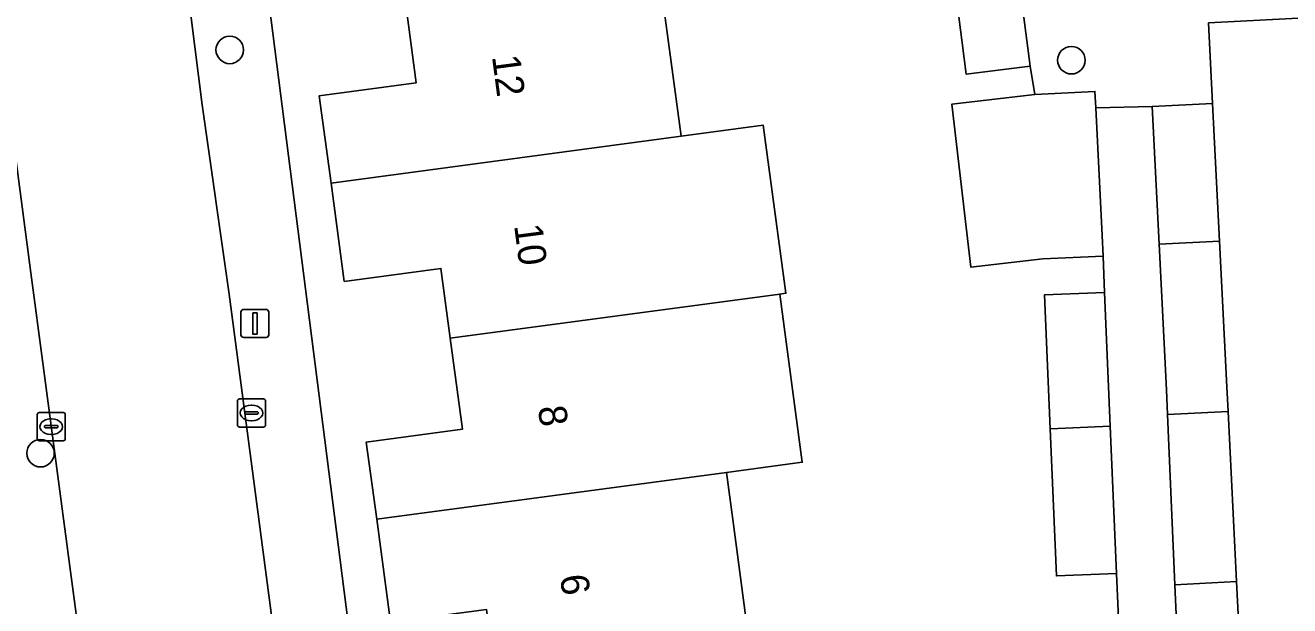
# Model space of a CAD drawing. Extents: x 161084 to 161928, y 385354 to 386522.
# Drawn here: x 161256.68 to 161301.64, y 385899.73 to 385920.36 of the extents above; entities that cross this region are included whole.
import ezdxf

# ---------------------------------------------------------------- set-up
doc = ezdxf.new("R2010")
doc.units = 0
for name, color, linetype in [('IMGEO_Boom', 7, 'Continuous'), ('IMGEO_Erf', 7, 'Continuous'), ('IMGEO_Kolk', 7, 'Continuous'), ('IMGEO_Lichtmast', 7, 'Continuous'), ('IMGEO_Pand', 7, 'Continuous'), ('IMGEO_Pand_nummerreeks', 7, 'Continuous'), ('IMGEO_Rijbaan_lokaal_open', 7, 'Continuous'), ('IMGEO_Voetpad_open', 7, 'Continuous')]:
    doc.layers.add(name, color=color, linetype=linetype)

msp = doc.modelspace()

# ---------------------------------------------------------------- linework, layer by layer
at = {"layer": 'IMGEO_Boom'}
for centre in [(161263.949, 385919.488), (161293.875, 385919.121), (161257.222, 385905.148)]:
    msp.add_circle(centre, 0.489, dxfattribs=at)
at = {"layer": 'IMGEO_Erf'}
for points in [[(161263.568, 385935.025), (161269.725, 385886.874)], [(161286.845, 385886.525), (161289.925, 385886.655), (161293.004, 385886.785), (161293.943, 385886.825), (161296.084, 385886.915), (161296.008, 385888.692), (161293.867, 385888.6), (161293.638, 385893.923), (161293.436, 385898.643), (161295.576, 385898.735), (161295.484, 385900.878), (161293.344, 385900.786), (161293.119, 385906.013), (161292.914, 385910.777), (161295.055, 385910.869), (161295, 385912.152), (161292.859, 385912.061), (161290.297, 385911.765), (161289.627, 385917.565), (161292.571, 385917.905), (161292.404, 385918.912), (161290.135, 385918.622), (161289.517, 385923.466)], [(161279.2, 385922.394), (161280.002, 385916.419), (161282.92, 385916.811), (161283.722, 385910.836), (161283.504, 385910.807), (161284.307, 385904.83), (161281.607, 385904.468), (161281.832, 385902.791), (161282.409, 385898.493)], [(161325.018, 385898.655), (161324.711, 385904.648), (161324.394, 385910.84), (161324.09, 385916.792), (161323.835, 385921.765), (161298.756, 385920.449), (161298.899, 385917.584), (161299.144, 385912.692), (161299.404, 385907.511), (161299.448, 385906.638), (161299.751, 385900.585), (161300.054, 385894.529), (161300.357, 385888.476), (161300.63, 385883.012), (161300.661, 385882.421), (161300.891, 385878.117), (161298.585, 385877.992), (161298.584, 385877.782), (161323.674, 385871.676)], [(161269.664, 385899.139), (161269.173, 385902.799), (161268.804, 385905.545), (161272.222, 385906.004), (161271.788, 385909.234), (161271.455, 385911.718), (161268.02, 385911.257), (161267.551, 385914.748), (161267.134, 385917.858), (161270.583, 385918.321), (161270.199, 385921.186)]]:
    msp.add_lwpolyline(points, dxfattribs=at)
at = {"layer": 'IMGEO_Kolk'}
for p, q in [((161264.223, 385906.154), (161264.223, 385907.006)), ((161264.298, 385907.08), (161265.15, 385907.08)), ((161264.711, 385906.86), (161264.736, 385906.86)), ((161265.224, 385907.006), (161265.224, 385906.154)), ((161257.101, 385905.668), (161257.101, 385906.52)), ((161257.176, 385906.594), (161258.028, 385906.594)), ((161257.589, 385906.374), (161257.614, 385906.374)), ((161258.102, 385906.52), (161258.102, 385905.668)), ((161264.482, 385906.574), (161264.482, 385906.586)), ((161264.92, 385906.537), (161264.522, 385906.537)), ((161264.525, 385906.623), (161264.923, 385906.623)), ((161264.966, 385906.586), (161264.966, 385906.574)), ((161257.36, 385906.088), (161257.36, 385906.1)), ((161257.798, 385906.051), (161257.4, 385906.051)), ((161257.403, 385906.137), (161257.801, 385906.137)), ((161257.844, 385906.1), (161257.844, 385906.088)), ((161265.15, 385906.08), (161264.298, 385906.08)), ((161264.734, 385906.3), (161264.709, 385906.3)), ((161258.028, 385905.594), (161257.176, 385905.594)), ((161257.612, 385905.814), (161257.587, 385905.814))]:
    msp.add_line(p, q, dxfattribs=at)
for points in [[(161264.223, 385906.154), (161264.223, 385907.006)], [(161264.298, 385907.08), (161265.15, 385907.08)], [(161265.224, 385907.006), (161265.224, 385906.154)], [(161257.101, 385905.668), (161257.101, 385906.52)], [(161257.176, 385906.594), (161258.028, 385906.594)], [(161258.102, 385906.52), (161258.102, 385905.668)], [(161265.15, 385906.08), (161264.298, 385906.08)], [(161258.028, 385905.594), (161257.176, 385905.594)]]:
    msp.add_lwpolyline(points, dxfattribs=at)
for centre, radius, start, end in [((161264.3, 385907.004), 0.0765, 91.552, 178.448), ((161264.3, 385907.004), 0.0765, 91.552, 178.448), ((161265.148, 385907.004), 0.0765, 1.552, 88.448), ((161265.148, 385907.004), 0.0765, 1.552, 88.448), ((161257.178, 385906.518), 0.0765, 91.552, 178.448), ((161257.178, 385906.518), 0.0765, 91.552, 178.448), ((161258.026, 385906.518), 0.0765, 1.552, 88.448), ((161258.026, 385906.518), 0.0765, 1.552, 88.448), ((161264.522, 385906.583), 0.0403, 85.8775, 175.7526), ((161264.519, 385906.573), 0.0366, 178.938, 274.7102), ((161264.923, 385906.58), 0.043, 264.8664, 352.4533), ((161264.927, 385906.585), 0.0386, 1.7309, 96.639), ((161257.4, 385906.097), 0.0403, 85.8775, 175.7526), ((161257.397, 385906.087), 0.0366, 178.938, 274.7102), ((161257.801, 385906.094), 0.043, 264.8664, 352.4533), ((161257.805, 385906.099), 0.0386, 1.7309, 96.639), ((161264.3, 385906.156), 0.0765, 181.552, 268.448), ((161264.3, 385906.156), 0.0765, 181.552, 268.448), ((161265.148, 385906.156), 0.0765, 271.552, 358.448), ((161265.148, 385906.156), 0.0765, 271.552, 358.448), ((161257.178, 385905.67), 0.0765, 181.552, 268.448), ((161257.178, 385905.67), 0.0765, 181.552, 268.448), ((161258.026, 385905.67), 0.0765, 271.552, 358.448), ((161258.026, 385905.67), 0.0765, 271.552, 358.448)]:
    msp.add_arc(centre, radius, start, end, dxfattribs=at)
for centre, major_axis, ratio, start_param, end_param in [((161264.71, 385906.58), (-0.387, 0.002), 0.722429, 4.712389, 7.853982), ((161264.735, 385906.58), (-0.39, 0.002), 0.717154, 1.570796, 4.712389), ((161257.588, 385906.094), (-0.387, 0.002), 0.722429, 4.712389, 7.853982), ((161257.613, 385906.094), (-0.39, 0.002), 0.717154, 1.570796, 4.712389)]:
    msp.add_ellipse(centre, major_axis=major_axis, ratio=ratio, start_param=start_param, end_param=end_param, dxfattribs=at)
at = {"layer": 'IMGEO_Lichtmast'}
for p, q in [((161264.348, 385909.362), (161264.348, 385910.162)), ((161264.348, 385910.162), (161264.348, 385909.362)), ((161264.448, 385910.262), (161265.238, 385910.262)), ((161265.238, 385910.262), (161264.448, 385910.262)), ((161265.338, 385910.162), (161265.338, 385909.362)), ((161265.338, 385909.362), (161265.338, 385910.162)), ((161265.238, 385909.262), (161264.448, 385909.262)), ((161264.448, 385909.262), (161265.238, 385909.262))]:
    msp.add_line(p, q, dxfattribs=at)
msp.add_lwpolyline([(161264.768, 385910.137), (161264.918, 385910.137), (161264.918, 385909.387), (161264.768, 385909.387), (161264.768, 385910.137)], dxfattribs=at)
for centre, start, end in [((161264.448, 385910.162), 90, 180), ((161264.448, 385910.162), 90, 180), ((161265.238, 385910.162), 0, 90), ((161265.238, 385910.162), 360, 90), ((161264.448, 385909.362), 180, 270), ((161264.448, 385909.362), 180, 270), ((161265.238, 385909.362), 270, 0), ((161265.238, 385909.362), 270, 0)]:
    msp.add_arc(centre, 0.1, start, end, dxfattribs=at)
at = {"layer": 'IMGEO_Pand'}
for points in [[(161291.786, 385923.756), (161291.317, 385923.696), (161289.517, 385923.466), (161290.135, 385918.622), (161292.404, 385918.912)], [(161280.002, 385916.419), (161279.2, 385922.394), (161270.199, 385921.186), (161270.583, 385918.321), (161267.134, 385917.858), (161267.551, 385914.748)], [(161294.74, 385917.43), (161294.711, 385918.012), (161292.571, 385917.905), (161289.627, 385917.565), (161290.297, 385911.765), (161292.859, 385912.061), (161295, 385912.152), (161294.968, 385912.888)], [(161296.751, 385917.476), (161296.997, 385912.579), (161299.144, 385912.692), (161298.899, 385917.584)], [(161282.92, 385916.811), (161280.002, 385916.419), (161267.551, 385914.748), (161268.02, 385911.257), (161271.455, 385911.718), (161271.788, 385909.234), (161283.504, 385910.807), (161283.722, 385910.836)], [(161299.448, 385906.638), (161299.404, 385907.511), (161299.144, 385912.692), (161296.997, 385912.579), (161297.256, 385907.403), (161297.294, 385906.525)], [(161295.055, 385910.869), (161292.914, 385910.777), (161293.119, 385906.013), (161293.133, 385906.015), (161295.259, 385906.106)], [(161283.504, 385910.807), (161271.788, 385909.234), (161272.222, 385906.004), (161268.804, 385905.545), (161269.173, 385902.799), (161281.607, 385904.468), (161284.307, 385904.83)], [(161299.751, 385900.585), (161299.448, 385906.638), (161297.294, 385906.525), (161297.558, 385900.471)], [(161295.259, 385906.106), (161293.133, 385906.015), (161293.119, 385906.013), (161293.344, 385900.786), (161295.484, 385900.878)], [(161282.409, 385898.493), (161281.832, 385902.791), (161281.607, 385904.468), (161269.173, 385902.799), (161269.664, 385899.139), (161273.076, 385899.597), (161273.387, 385897.282)], [(161300.054, 385894.529), (161299.751, 385900.585), (161297.558, 385900.471), (161297.822, 385894.411)]]:
    msp.add_lwpolyline(points, close=True, dxfattribs=at)
at = {"layer": 'IMGEO_Rijbaan_lokaal_open'}
for points in [[(161248.067, 385978.597), (161256.871, 385911.557), (161257.309, 385908.263), (161258.033, 385902.817), (161258.922, 385896.131), (161260.168, 385886.756), (161260.415, 385885.391), (161260.782, 385884.053), (161261.033, 385883.337), (161261.516, 385882.059), (161262.143, 385880.777), (161262.923, 385879.579), (161263.827, 385878.528), (161264.804, 385877.517), (161265.77, 385876.664), (161266.781, 385875.85), (161267.827, 385875.24), (161268.907, 385874.769), (161270.024, 385874.279), (161271.217, 385873.952), (161271.458, 385873.896), (161276.452, 385872.742), (161278.079, 385879.424), (161273.199, 385880.655)], [(161267.007, 385887.426), (161263.934, 385910.799), (161262.973, 385917.539), (161260.642, 385935.92)], [(161291.786, 385923.756), (161292.404, 385918.912), (161292.571, 385917.905), (161294.711, 385918.012), (161294.74, 385917.43), (161296.751, 385917.476), (161298.899, 385917.584), (161298.756, 385920.449)]]:
    msp.add_lwpolyline(points, dxfattribs=at)
at = {"layer": 'IMGEO_Voetpad_open'}
for points in [[(161269.725, 385886.874), (161263.568, 385935.025), (161263.263, 385937.353), (161258.189, 385975.824), (161258.145, 385976.159), (161257.909, 385977.952), (161255.001, 386000), (161252.413, 386019.447)], [(161260.642, 385935.92), (161262.973, 385917.539), (161263.934, 385910.799), (161267.007, 385887.426)]]:
    msp.add_lwpolyline(points, dxfattribs=at)
for points in [[(161248.067, 385978.597), (161247.586, 385978.531), (161246.916, 385983.683), (161245.002, 385983.429), (161245.764, 385976.325), (161247.222, 385965.488), (161249.386, 385949.483), (161252.002, 385929.347), (161258.188, 385882.488), (161259.346, 385874.464), (161263.827, 385878.528), (161262.923, 385879.579), (161262.143, 385880.777), (161261.516, 385882.059), (161261.033, 385883.337), (161260.782, 385884.053), (161260.415, 385885.391), (161260.168, 385886.756), (161258.922, 385896.131), (161258.033, 385902.817), (161257.309, 385908.263), (161256.871, 385911.557)], [(161297.558, 385900.471), (161297.294, 385906.525), (161297.256, 385907.403), (161296.997, 385912.579), (161296.751, 385917.476), (161294.74, 385917.43), (161294.968, 385912.888), (161295, 385912.152), (161295.055, 385910.869), (161295.259, 385906.106), (161295.484, 385900.878), (161295.576, 385898.735), (161295.779, 385894.015), (161296.008, 385888.692), (161296.084, 385886.915), (161296.394, 385880.953), (161293.256, 385880.821), (161290.177, 385880.691), (161287.155, 385880.563), (161298.584, 385877.782), (161298.585, 385877.992), (161298.355, 385882.3), (161298.086, 385888.357), (161297.822, 385894.411)]]:
    msp.add_lwpolyline(points, close=True, dxfattribs=at)

# ---------------------------------------------------------------- texts
at = {"layer": 'IMGEO_Pand_nummerreeks'}
for s, rotation, p in [('12', 277.4538, (161273.272, 385919.255)), ('10', 277.454, (161274.058, 385913.246)), ('8', 277.454, (161274.904, 385906.786)), ('6', 277.4538, (161275.688, 385900.786))]:
    msp.add_text(s, height=1, rotation=rotation, dxfattribs=at).set_placement(p)

doc.saveas('drawing.dxf')
